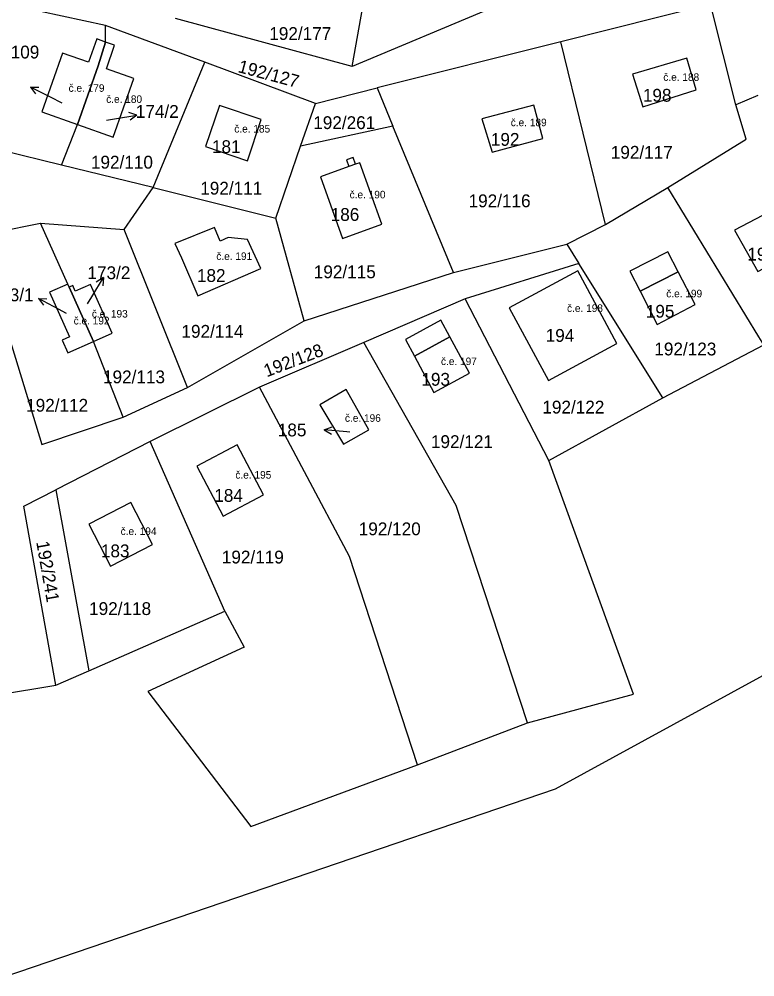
# Model space of a CAD drawing. Extents: x -887272 to -877616, y -1026687 to -1019819.
# Drawn here: x -882299.4 to -882201.9, y -1024320.7 to -1024193.7 of the extents above; entities that cross this region are included whole.
import ezdxf

# ---------------------------------------------------------------- set-up
doc = ezdxf.new("R2010")
doc.units = 0
for name, color, linetype in [('Definiční body', 7, 'Continuous'), ('Hranice parcel', 7, 'Continuous'), ('Parcelní čísla', 7, 'Continuous'), ('Polygon budovy', 7, 'Continuous'), ('Pop  PČ popisy', 7, 'Continuous'), ('Vnitřní kresba', 7, 'Continuous')]:
    doc.layers.add(name, color=color, linetype=linetype)

msp = doc.modelspace()

# ---------------------------------------------------------------- linework, layer by layer
at = {"layer": 'Hranice parcel'}
for p, q in [((-882255.25, -1024200.01), (-882252.31, -1024183.68)), ((-882207.74, -1024191.74), (-882227.58, -1024196.72)), ((-882204.37, -1024205.08), (-882207.74, -1024191.74)), ((-882236.46, -1024192.13), (-882255.25, -1024200.01)), ((-882255.25, -1024200.01), (-882278.63, -1024193.63)), ((-882287.91, -1024196.76), (-882287.91, -1024194.55)), ((-882274.77, -1024199.44), (-882287.91, -1024194.55)), ((-882227.58, -1024196.72), (-882251.93, -1024202.84)), ((-882221.64, -1024220.93), (-882227.58, -1024196.72)), ((-882281.59, -1024216.03), (-882274.77, -1024199.44)), ((-882260.11, -1024204.89), (-882274.77, -1024199.44)), ((-882260.11, -1024204.89), (-882251.93, -1024202.84)), ((-882251.93, -1024202.84), (-882249.83, -1024207.92)), ((-882201.44, -1024203.82), (-882204.37, -1024205.08)), ((-882262.06, -1024210.54), (-882260.11, -1024204.89)), ((-882293.75, -1024213.08), (-882291.66, -1024207.69)), ((-882249.83, -1024207.92), (-882262.06, -1024210.54)), ((-882241.79, -1024227.32), (-882249.83, -1024207.92)), ((-882265.36, -1024220.09), (-882262.06, -1024210.54)), ((-882281.59, -1024216.03), (-882293.75, -1024213.08)), ((-882285.44, -1024221.62), (-882281.59, -1024216.03)), ((-882281.59, -1024216.03), (-882265.36, -1024220.09)), ((-882221.64, -1024220.93), (-882213.38, -1024216.04)), ((-882304.86, -1024222.45), (-882296.53, -1024220.75)), ((-882292.94, -1024228.83), (-882296.53, -1024220.75)), ((-882296.53, -1024220.75), (-882285.44, -1024221.62)), ((-882261.58, -1024233.71), (-882265.36, -1024220.09)), ((-882226.76, -1024223.54), (-882221.64, -1024220.93)), ((-882277.04, -1024242.53), (-882285.44, -1024221.62)), ((-882241.79, -1024227.32), (-882226.76, -1024223.54)), ((-882226.76, -1024223.54), (-882225.17, -1024226.09)), ((-882225.17, -1024226.09), (-882240.26, -1024230.81)), ((-882214.06, -1024243.9), (-882225.17, -1024226.09)), ((-882261.58, -1024233.71), (-882241.79, -1024227.32)), ((-882292.75, -1024229.25), (-882292.94, -1024228.83)), ((-882289.52, -1024236.46), (-882292.75, -1024229.25)), ((-882240.26, -1024230.81), (-882253.67, -1024236.56)), ((-882229.17, -1024252.22), (-882240.26, -1024230.81)), ((-882277.04, -1024242.53), (-882261.58, -1024233.71)), ((-882285.58, -1024246.47), (-882289.52, -1024236.46)), ((-882253.67, -1024236.56), (-882267.53, -1024242.5)), ((-882214.06, -1024243.9), (-882200.68, -1024236.89)), ((-882285.58, -1024246.47), (-882277.04, -1024242.53)), ((-882267.53, -1024242.5), (-882282.01, -1024249.71)), ((-882229.17, -1024252.22), (-882214.06, -1024243.9)), ((-882282.01, -1024249.71), (-882294.5, -1024256.1)), ((-882272.1, -1024272.18), (-882282.01, -1024249.71)), ((-882294.5, -1024256.1), (-882290.13, -1024280.09)), ((-882287.25, -1024266.21), (-882281.69, -1024263.34)), ((-882290.13, -1024280.09), (-882272.1, -1024272.18)), ((-882294.5, -1024282), (-882290.13, -1024280.09)), ((-882305.94, -1024283.91), (-882294.5, -1024282)), ((-882246.57, -1024292.54), (-882231.98, -1024287))]:
    msp.add_line(p, q, dxfattribs=at)
for points in [[(-882287.91, -1024194.55), (-882302.33, -1024191.49), (-882307.87, -1024198.55)], [(-882425.59, -1024292.38), (-882421.44, -1024309.52), (-882387.34, -1024318.62), (-882335.2, -1024317.62), (-882324.6, -1024318.36), (-882301.38, -1024320.66), (-882228.26, -1024295.72), (-882166.04, -1024261.72), (-882132.4, -1024219.02), (-882083.16, -1024195.4)], [(-882287.91, -1024196.76), (-882289.09, -1024196.35), (-882290.17, -1024199.42), (-882293.65, -1024198.24), (-882296.39, -1024206.02), (-882291.66, -1024207.69)], [(-882291.66, -1024207.69), (-882288.91, -1024199.91), (-882287.91, -1024196.76)], [(-882291.66, -1024207.69), (-882286.93, -1024209.36), (-882284.18, -1024201.58), (-882287.81, -1024200.29), (-882286.72, -1024197.18), (-882287.91, -1024196.76)], [(-882293.75, -1024213.08), (-882301.69, -1024211.15), (-882307.87, -1024198.55)], [(-882210.86, -1024198.88), (-882218.06, -1024201), (-882216.7, -1024205.32), (-882209.64, -1024203.1), (-882210.86, -1024198.88)], [(-882269.12, -1024212.48), (-882267.28, -1024207.04), (-882272.82, -1024205.16), (-882274.66, -1024210.6), (-882269.12, -1024212.48)], [(-882238.06, -1024206.92), (-882236.68, -1024211.34), (-882229.98, -1024209.54), (-882231.17, -1024205.1), (-882238.06, -1024206.92)], [(-882213.38, -1024216.04), (-882203.01, -1024209.61), (-882204.37, -1024205.08)], [(-882251.3, -1024220.9), (-882254.23, -1024212.75), (-882254.79, -1024212.95), (-882255.11, -1024212.06), (-882255.98, -1024212.38), (-882255.66, -1024213.27), (-882259.45, -1024214.63), (-882256.52, -1024222.78), (-882251.3, -1024220.9)], [(-882200.68, -1024236.89), (-882201.33, -1024235.82), (-882213.38, -1024216.04)], [(-882201.44, -1024227.17), (-882195.88, -1024224.22), (-882199, -1024218.76), (-882204.57, -1024221.7), (-882201.44, -1024227.17)], [(-882272.74, -1024223.14), (-882273.48, -1024221.33), (-882278.76, -1024223.45), (-882277.87, -1024225.35), (-882275.68, -1024230.39), (-882267.34, -1024226.76), (-882269.11, -1024222.93), (-882271.67, -1024222.67), (-882272.74, -1024223.14)], [(-882304.86, -1024222.45), (-882296.39, -1024250.09), (-882285.58, -1024246.47)], [(-882212, -1024227.22), (-882213.39, -1024224.56), (-882218.41, -1024227.12), (-882217.04, -1024229.79), (-882214.79, -1024234.19), (-882209.75, -1024231.53), (-882212, -1024227.22)], [(-882229.23, -1024241.61), (-882220.13, -1024236.69), (-882225.33, -1024227.08), (-882234.44, -1024231.98), (-882229.23, -1024241.61)], [(-882292.94, -1024228.83), (-882295.35, -1024229.9), (-882292.71, -1024235.84), (-882293.66, -1024236.26), (-882292.91, -1024237.96), (-882289.52, -1024236.46)], [(-882289.52, -1024236.46), (-882287.04, -1024235.36), (-882289.91, -1024228.89), (-882291.94, -1024229.79), (-882292.27, -1024229.04), (-882292.75, -1024229.25)], [(-882246.98, -1024238.4), (-882244.42, -1024243.2), (-882239.66, -1024240.66), (-882242.29, -1024235.83), (-882243.49, -1024233.63), (-882248.15, -1024236.2), (-882246.98, -1024238.4)], [(-882231.98, -1024287), (-882241.44, -1024258.19), (-882253.67, -1024236.56)], [(-882246.57, -1024292.54), (-882255.59, -1024264.95), (-882267.53, -1024242.5)], [(-882259.52, -1024244.82), (-882256.38, -1024250.06), (-882253.04, -1024248.16), (-882256.04, -1024242.8), (-882259.52, -1024244.82)], [(-882272.32, -1024259.58), (-882266.97, -1024256.76), (-882270.46, -1024250.13), (-882275.81, -1024252.95), (-882272.32, -1024259.58)], [(-882231.98, -1024287), (-882217.96, -1024283.21), (-882229.17, -1024252.22)], [(-882294.5, -1024282), (-882298.74, -1024258.26), (-882294.5, -1024256.1)], [(-882281.69, -1024263.34), (-882284.56, -1024257.78), (-882290.12, -1024260.65), (-882287.25, -1024266.21)], [(-882272.1, -1024272.18), (-882269.56, -1024276.98), (-882282.34, -1024282.85), (-882268.67, -1024300.71), (-882246.57, -1024292.54)]]:
    msp.add_lwpolyline(points, dxfattribs=at)
at = {"layer": 'Polygon budovy'}
for points in [[(-882293.65, -1024198.24), (-882296.39, -1024206.02), (-882291.66, -1024207.69), (-882288.91, -1024199.91), (-882287.91, -1024196.76), (-882289.09, -1024196.35), (-882290.17, -1024199.42)], [(-882291.66, -1024207.69), (-882286.93, -1024209.36), (-882284.18, -1024201.58), (-882287.81, -1024200.29), (-882286.72, -1024197.18), (-882287.91, -1024196.76), (-882288.91, -1024199.91)], [(-882218.06, -1024201), (-882216.7, -1024205.32), (-882209.64, -1024203.1), (-882210.86, -1024198.88)], [(-882267.28, -1024207.04), (-882272.82, -1024205.16), (-882274.66, -1024210.6), (-882269.12, -1024212.48)], [(-882229.98, -1024209.54), (-882231.17, -1024205.1), (-882238.06, -1024206.92), (-882236.68, -1024211.34)], [(-882259.45, -1024214.63), (-882256.52, -1024222.78), (-882251.3, -1024220.9), (-882254.23, -1024212.75), (-882254.79, -1024212.95), (-882255.66, -1024213.27)], [(-882195.88, -1024224.22), (-882199, -1024218.76), (-882204.57, -1024221.7), (-882201.44, -1024227.17)], [(-882271.67, -1024222.67), (-882272.74, -1024223.14), (-882273.48, -1024221.33), (-882278.76, -1024223.45), (-882277.87, -1024225.35), (-882275.68, -1024230.39), (-882267.34, -1024226.76), (-882269.11, -1024222.93)], [(-882234.44, -1024231.98), (-882229.23, -1024241.61), (-882220.13, -1024236.69), (-882225.33, -1024227.08)], [(-882217.04, -1024229.79), (-882214.79, -1024234.19), (-882209.75, -1024231.53), (-882212, -1024227.22)], [(-882292.91, -1024237.96), (-882289.52, -1024236.46), (-882292.75, -1024229.25), (-882292.94, -1024228.83), (-882295.35, -1024229.9), (-882292.71, -1024235.84), (-882293.66, -1024236.26)], [(-882292.75, -1024229.25), (-882289.52, -1024236.46), (-882287.04, -1024235.36), (-882289.91, -1024228.89), (-882291.94, -1024229.79), (-882292.27, -1024229.04)], [(-882244.42, -1024243.2), (-882239.66, -1024240.66), (-882242.29, -1024235.83), (-882246.98, -1024238.4)], [(-882256.04, -1024242.8), (-882259.52, -1024244.82), (-882256.38, -1024250.06), (-882253.04, -1024248.16)], [(-882266.97, -1024256.76), (-882270.46, -1024250.13), (-882275.81, -1024252.95), (-882272.32, -1024259.58)], [(-882287.25, -1024266.21), (-882281.69, -1024263.34), (-882284.56, -1024257.78), (-882290.12, -1024260.65)]]:
    msp.add_lwpolyline(points, close=True, dxfattribs=at)
at = {"layer": 'Pop  PČ popisy'}
for p, q in [((-882295.21, -1024204.08), (-882297.88, -1024202.72)), ((-882297.88, -1024202.72), (-882296.76, -1024202.73)), ((-882297.88, -1024202.72), (-882297.22, -1024203.62)), ((-882293.67, -1024204.87), (-882295.21, -1024204.08)), ((-882287.8, -1024207.09), (-882286.72, -1024206.92)), ((-882286.72, -1024206.92), (-882283.76, -1024206.45)), ((-882283.76, -1024206.45), (-882284.82, -1024206.11)), ((-882283.76, -1024206.45), (-882284.67, -1024207.1)), ((-882289.75, -1024230.54), (-882288.2, -1024227.97)), ((-882288.2, -1024227.97), (-882289.15, -1024228.57)), ((-882288.2, -1024227.97), (-882288.29, -1024229.08)), ((-882294.16, -1024232.15), (-882296.81, -1024230.74)), ((-882296.81, -1024230.74), (-882295.69, -1024230.77)), ((-882296.81, -1024230.74), (-882296.16, -1024231.65)), ((-882290.3, -1024231.46), (-882289.75, -1024230.54)), ((-882293.08, -1024232.72), (-882294.16, -1024232.15)), ((-882258.93, -1024248.16), (-882257.89, -1024247.75)), ((-882255.94, -1024248.42), (-882258.93, -1024248.16)), ((-882258.93, -1024248.16), (-882257.98, -1024248.74)), ((-882255.56, -1024248.45), (-882255.94, -1024248.42))]:
    msp.add_line(p, q, dxfattribs=at)
at = {"layer": 'Vnitřní kresba'}
for p, q in [((-882254.79, -1024212.95), (-882255.66, -1024213.27)), ((-882217.04, -1024229.79), (-882212, -1024227.22)), ((-882246.98, -1024238.4), (-882242.29, -1024235.83))]:
    msp.add_line(p, q, dxfattribs=at)

# ---------------------------------------------------------------- texts
at = {"layer": 'Definiční body'}
for s, p in [('č.e. 188', (-882213.99, -1024201.9)), ('č.e. 179', (-882292.82, -1024203.35)), ('č.e. 180', (-882287.84, -1024204.82)), ('č.e. 189', (-882234.21, -1024207.91)), ('č.e. 185', (-882270.86, -1024208.75)), ('č.e. 190', (-882255.57, -1024217.47)), ('č.e. 191', (-882273.24, -1024225.64)), ('č.e. 199', (-882213.6, -1024230.59)), ('č.e. 193', (-882289.74, -1024233.27)), ('č.e. 198', (-882226.75, -1024232.53)), ('č.e. 192', (-882292.15, -1024234.19)), ('č.e. 197', (-882243.46, -1024239.57)), ('č.e. 196', (-882256.19, -1024247.09)), ('č.e. 195', (-882270.71, -1024254.62)), ('č.e. 194', (-882285.92, -1024262.09))]:
    msp.add_text(s, height=1, dxfattribs=at).set_placement(p)
at = {"layer": 'Parcelní čísla'}
for s, p in [('192/177', (-882266.22, -1024196.48)), ('192/109', (-882304.92, -1024198.93)), ('198', (-882216.7, -1024204.66)), ('174/2', (-882283.91, -1024206.8)), ('192/261', (-882260.39, -1024208.29)), ('192', (-882236.85, -1024210.51)), ('181', (-882273.82, -1024211.47)), ('192/117', (-882220.95, -1024212.22)), ('192/110', (-882289.86, -1024213.53)), ('192/111', (-882275.37, -1024216.98)), ('192/116', (-882239.8, -1024218.65)), ('186', (-882258.08, -1024220.46)), ('196', (-882202.85, -1024225.71)), ('173/2', (-882290.32, -1024228.18)), ('182', (-882275.81, -1024228.55)), ('192/115', (-882260.32, -1024228.06)), ('173/1', (-882303.15, -1024231.11)), ('195', (-882216.31, -1024233.29)), ('192/114', (-882277.86, -1024235.95)), ('194', (-882229.58, -1024236.49)), ('192/123', (-882215.18, -1024238.29)), ('192/113', (-882288.26, -1024241.99)), ('193', (-882246.06, -1024242.31)), ('192/112', (-882298.45, -1024245.75)), ('192/122', (-882230.02, -1024245.99)), ('185', (-882265.09, -1024249.02)), ('192/121', (-882244.79, -1024250.57)), ('184', (-882273.51, -1024257.7)), ('192/120', (-882254.36, -1024262.13)), ('183', (-882288.54, -1024265.05)), ('192/119', (-882272.51, -1024265.87)), ('192/118', (-882290.1, -1024272.7))]:
    msp.add_text(s, height=1.7, dxfattribs=at).set_placement(p)
for s, rotation, p in [('192/127', 345, (-882270.48, -1024200.72)), ('192/128', 21, (-882266.56, -1024241.2)), ('192/241', 280, (-882297.12, -1024263.03))]:
    msp.add_text(s, height=1.7, rotation=rotation, dxfattribs=at).set_placement(p)

doc.saveas('drawing.dxf')
